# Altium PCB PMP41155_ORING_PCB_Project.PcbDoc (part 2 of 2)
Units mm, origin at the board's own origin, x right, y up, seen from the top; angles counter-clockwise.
Board outline 28 x 74 mm, 6 copper layers (Top Layer, Layer 2, Layer 3, Layer 4, Layer 5, Bottom Layer), stack 1.284 mm thick; 32 components, 11 nets, 88 pads, 180 vias.
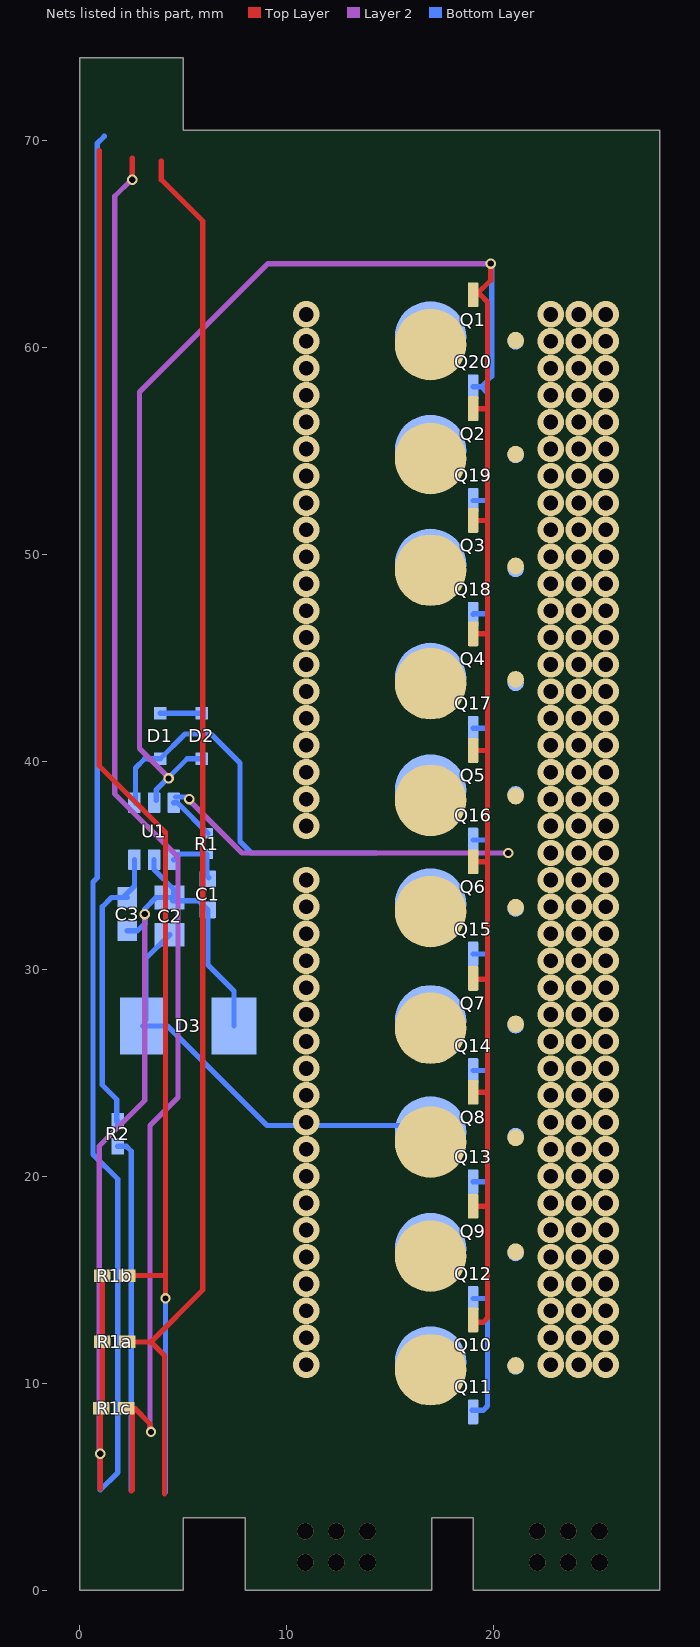
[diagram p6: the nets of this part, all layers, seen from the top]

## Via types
v1: diameter 1.27, hole 0.711, Top Layer to Bottom Layer, 159 vias
v2: diameter 0.8, hole 0.8, Top Layer to Bottom Layer, 12 vias
v3: diameter 0.5, hole 0.3, Top Layer to Bottom Layer, 9 vias

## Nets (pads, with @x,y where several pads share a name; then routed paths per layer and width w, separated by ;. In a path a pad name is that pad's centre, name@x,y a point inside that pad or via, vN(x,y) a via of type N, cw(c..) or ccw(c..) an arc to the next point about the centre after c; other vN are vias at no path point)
CS+_total_charge_current_battery: R1a.2 | length 67.6
  Top Layer w0.254: R1a.2@2.3,12 3.45,12 ; 3.95,69 3.95,68.1 5.95,66.1 5.95,14.5 3.45,12 ; 4.1,4.669 4.1,11.35 3.45,12
CS-_total_charge_current_battery: R1c.2 | length 69
  Top Layer w0.254: 2.5,4.8 2.55,4.85 R1c.2@2.55,8.8 ; v3(2.55,68.1) 2.55,69.15 ; 2.65,8.8 3.4,8.05 v3@3.4,7.8
  Layer 2 w0.254: v3@2.55,68.15 1.7,67.3 1.7,38.45 4.75,35.4 4.75,23.8 3.4,22.45 v3@3.4,7.7
  other v3: 3.452,7.654
NetC1_2: C1.2 R1.1 U1.1 | length 2.9
  Bottom Layer w0.254: U1.1@4.55,35.275 4.825,35.55 R1.1@6.15,35.55 6.15,34.5 C1.2@6.25,34.4
NetC3_1: C3.1 R2.2 U1.3 | length 14.2
  Bottom Layer w0.254: R2.2@1.8,22.65 1.8,23.7 1.1,24.4 1.1,33 1.55,33.45 C3.1@2.3,33.45 ; R2.2@1.85,22.479 R2.2@1.85,22.65 ; C3.1@2.1,33.45 2.65,34 U1.3@2.65,35.275
NetD1_1: D1.1 D2.1 | length 2.1
  Bottom Layer w0.254: D1.1@3.9,42.35 D2.1@5.9,42.35 D2.1@5.95,42.3
ORING_CONTROL: D2.2 Q1.9 Q2.9 Q3.9 Q4.9 Q5.9 Q6.9 Q7.9 Q8.9 Q9.9 Q10.9 Q11.9 Q12.9 Q13.9 Q14.9 Q15.9 Q16.9 Q17.9 Q18.9 Q19.9 Q20.9 U1.5 | length 162.1
  Top Layer w0.254: Q10.9@18.95,12.95 19.5,12.95 19.7,13.15 19.7,18.55 ; Q9.9@19.001,18.55 19.7,18.55 ; Q8.9@19.001,24.05 19.65,24.05 19.7,24.1 ; Q7.9@19.001,29.55 19.05,29.5 19.7,29.5 ; Q6.9@19.001,35.18 19.67,35.18 19.7,35.15 ; Q5.9@19.001,40.55 19.7,40.55 ; Q4.9@19.001,46.18 19.68,46.18 19.7,46.2 ; Q3.9@19.001,51.655 19.695,51.655 19.7,51.65 ; Q2.9@19.001,57.05 19.7,57.05 ; Q1.9@19.2,62.55 19.35,62.55 19.7,62.2 19.7,57.05 ; Q1.9@19.2,62.6 19.85,63.25 v3(19.85,64.05) ; 19.7,18.55 19.7,24.1 ; 19.7,24.1 19.7,29.5 ; 19.7,29.5 19.7,35.15 ; 19.7,35.15 19.7,40.55 ; 19.7,40.55 19.7,46.2 ; 19.7,46.2 19.7,51.65 ; 19.7,51.65 19.7,57.05
  Layer 2 w0.254: v3@4.345,39.205 2.9,40.65 2.9,57.85 9.1,64.05 v3(19.85,64.05)
  Bottom Layer w0.254: U1.5@3.7,38.15 3.7,38.65 5.2,40.15 D2.2@5.9,40.15 ; Q11.9@18.95,8.7 19.5,8.7 19.7,8.9 19.7,25.1 ; Q12.9@19.001,14.095 19.595,14.095 19.6,14.1 ; Q13.9@19.001,19.725 19.625,19.725 19.65,19.75 ; Q14.9@19.001,25.095 19.695,25.095 19.7,25.1 ; Q15.9@19.001,30.725 19.675,30.725 19.7,30.7 ; Q16.9@19.001,36.225 19.675,36.225 19.7,36.2 ; Q17.9@19.001,41.62 19.67,41.62 19.7,41.65 ; Q18.9@19.001,47.12 19.03,47.15 19.65,47.15 ; Q19.9@19.001,52.62 19.62,52.62 19.65,52.65 ; Q20.9@19.001,58.109 19.391,58.109 ; v3@19.9,64.05 19.9,58.618 19.391,58.109 ; 19.391,58.109 19.7,57.8 19.7,41.65 ; 19.7,25.1 19.7,30.7 ; 19.7,30.7 19.7,36.2 ; 19.7,36.2 19.7,41.65
  other v3: 4.3,39.2
SGND: C1.1 C2.2 C3.2 D3.2 R1a.1 R1b.1 R1c.1 U1.2 | length 119
  Top Layer w0.254: 1,4.9 v3(1,6.6) 1,8.55 R1c.1@1.3,8.85 ; R1c.1@1.05,8.8 1.1,8.85 R1a.1@1.1,12 R1b.1@1.1,15.2
  Layer 2 w0.254: v3@0.95,6.65 0.95,21.45 3.15,23.65 v3(3.15,32.65)
  Bottom Layer w0.254: v3(1,6.6) 1,4.85 1.85,5.7 1.85,19.85 0.646,21.054 0.646,24.212 0.646,34.196 0.85,34.4 0.85,69.85 1.2,70.2 ; C3.2@2.3,31.85 2.8,31.85 3.15,32.2 v3(3.15,32.65) 3.15,32.9 3.7,33.45 C2.2@4.35,33.45 ; U1.2@3.6,35.275 3.6,34.8 4.55,33.85 C2.2@4.55,33.4 ; C2.2@4.5,33.3 5.75,33.3 C1.1@6.2,32.85 6.2,30.2 7.46,28.94 D3.2@7.46,27.25
UC_ORING_EN: R2.1 | length 17.1
  Bottom Layer w0.254: R2.1@1.85,21.45 2.25,21.45 2.5,21.2 2.5,4.853
VBAT: R1b.2 | length 67.9
  Top Layer w0.254: 0.95,69.5 0.95,39.8 4.15,36.6 4.15,15.2 ; R1b.2@2.3,15.2 4.15,15.2 ; v3(4.15,14.1) 4.15,15.2
  Bottom Layer w0.254: 4.15,4.73 v3(4.15,14.1)
VORING: Q1.5-6-7-8 Q2.5-6-7-8 Q3.5-6-7-8 Q4.5-6-7-8 Q5.5-6-7-8 Q6.5-6-7-8 Q7.5-6-7-8 Q8.5-6-7-8 Q9.5-6-7-8 Q10.5-6-7-8 Q11.5-6-7-8 Q12.5-6-7-8 Q13.5-6-7-8 Q14.5-6-7-8 Q15.5-6-7-8 Q16.5-6-7-8 Q17.5-6-7-8 Q18.5-6-7-8 Q19.5-6-7-8 Q20.5-6-7-8 R1.2 U1.6 | length 19.4
  Layer 2 w0.254: v3@5.312,38.138 7.85,35.6 v3(20.7,35.6)
  Bottom Layer w0.254: U1.6@4.55,38.025 4.725,38.025 R1.2@6.2,36.55 ; U1.6@4.65,38.3 5.2,38.3 v3(5.3,38.2)
  other v1: 22.75,10.9 24.1,10.9 25.4,10.9 22.75,12.2 24.1,12.2 25.4,12.2 22.75,13.5 24.1,13.5 25.4,13.5 22.75,14.8 24.1,14.8 25.4,14.8 22.75,16.1 24.1,16.1 25.4,16.1 22.75,17.4 24.1,17.4 25.4,17.4 22.75,18.7 24.1,18.7 25.4,18.7 22.75,20 24.1,20 25.4,20 22.75,21.3 24.1,21.3 25.4,21.3 22.75,22.6 24.1,22.6 25.4,22.6 22.75,23.9 24.1,23.9 25.4,23.9 22.75,25.2 24.1,25.2 25.4,25.2 22.75,26.5 24.1,26.5 25.4,26.5 22.75,27.8 24.1,27.8 25.4,27.8 22.75,29.1 24.1,29.1 25.4,29.1 22.75,30.4 24.1,30.4 25.4,30.4 22.75,31.7 24.1,31.7 25.4,31.7 22.75,33 24.1,33 25.4,33 22.75,34.3 24.1,34.3 25.4,34.3 22.75,35.6 24.1,35.6 25.4,35.6 22.75,36.9 24.1,36.9 25.4,36.9 22.75,38.2 24.1,38.2 25.4,38.2 22.75,39.5 24.1,39.5 25.4,39.5 22.75,40.8 24.1,40.8 25.4,40.8 22.75,42.1 24.1,42.1 25.4,42.1 22.75,43.4 24.1,43.4 25.4,43.4 22.75,44.7 24.1,44.7 25.4,44.7 22.75,46 24.1,46 25.4,46 22.75,47.3 24.1,47.3 25.4,47.3 22.75,48.6 24.1,48.6 25.4,48.6 22.75,49.9 24.1,49.9 25.4,49.9 22.75,51.2 24.1,51.2 25.4,51.2 22.75,52.5 24.1,52.5 25.4,52.5 22.75,53.8 24.1,53.8 25.4,53.8 22.75,55.1 24.1,55.1 25.4,55.1 22.75,56.4 24.1,56.4 25.4,56.4 22.75,57.7 24.1,57.7 25.4,57.7 22.75,59 24.1,59 25.4,59 22.75,60.3 24.1,60.3 25.4,60.3 22.75,61.6 24.1,61.6 25.4,61.6
  other v2: 22.1,1.35 23.6,1.35 25.1,1.35 22.1,2.85 23.6,2.85 25.1,2.85
VORING1: C2.1 D1.2 D3.1 Q1.1-2-3-4 Q2.1-2-3-4 Q3.1-2-3-4 Q4.1-2-3-4 Q5.1-2-3-4 Q6.1-2-3-4 Q7.1-2-3-4 Q8.1-2-3-4 Q9.1-2-3-4 Q10.1-2-3-4 Q11.1-2-3-4 Q12.1-2-3-4 Q13.1-2-3-4 Q14.1-2-3-4 Q15.1-2-3-4 Q16.1-2-3-4 Q17.1-2-3-4 Q18.1-2-3-4 Q19.1-2-3-4 Q20.1-2-3-4 U1.4 | length 37.8
  Bottom Layer w0.254: U1.4@2.7,38 2.7,39.7 3.15,40.15 D1.2@3.9,40.15 5.1,41.35 6.35,41.35 7.75,39.95 7.75,36.15 8.3,35.6 14.3,35.6 ; D3.1@3.04,27.25 4.25,27.25 9.05,22.45 10.95,22.45 Q13.1-2-3-4@15.65,22.45 ; D3.1@3.2,27.55 3.2,30.5 C2.1@4.35,31.65
  other v1: 10.95,10.9 10.95,12.2 10.95,13.5 10.95,14.8 10.95,16.1 10.95,17.4 10.95,18.7 10.95,20 10.95,21.3 10.95,22.6 10.95,23.9 10.95,25.2 10.95,26.5 10.95,27.8 10.95,29.1 10.95,30.4 10.95,31.7 10.95,33 10.95,34.3 10.95,36.9 10.95,38.2 10.95,39.5 10.95,40.8 10.95,42.1 10.95,43.4 10.95,44.7 10.95,46 10.95,47.3 10.95,48.6 10.95,49.9 10.95,51.2 10.95,52.5 10.95,53.8 10.95,55.1 10.95,56.4 10.95,57.7 10.95,59 10.95,60.3 10.95,61.6
  other v2: 10.9,1.35 12.4,1.35 13.9,1.35 10.9,2.85 12.4,2.85 13.9,2.85

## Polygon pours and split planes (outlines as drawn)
VORING1 on Top Layer "TOP_LAYER_VORING1_P002" (solid, pour order 2): 16.5,4.5 19.3,7.3 19.3,68.95 18.75,69.5 18.7,69.45 9.3,69.45 6.45,66.6 6.45,6.55 8.5,4.5
VORING on Top Layer "TOP_LAYER_VORING_P001" (solid, pour order 1): 20.55,4.95 20.55,69.15 20.9,69.5 27.1,69.5 27.35,69.25 27.35,4.3 21.2,4.3
VORING on Layer 2 "LAYER_2_VORING_P008" (solid, pour order 8): 20.55,4.95 20.55,69.15 20.9,69.5 27.1,69.5 27.35,69.25 27.35,4.3 21.2,4.3
VORING1 on Layer 2 "LAYER_2_VORING1_P003" (solid, pour order 3): 16.5,4.5 19.3,7.3 19.3,68.95 18.75,69.5 18.7,69.45 9.3,69.45 8.1,68.25 8.1,4.9 8.5,4.5
VORING on Layer 3 "LAYER_3_VORING_P007" (solid, pour order 7): 20.55,4.95 20.55,69.15 20.9,69.5 27.1,69.5 27.35,69.25 27.35,4.3 21.2,4.3
VORING1 on Layer 3 "LAYER_3_VORING1_P000" (solid, pour order 0): 16.5,4.5 19.3,7.3 19.3,68.95 18.75,69.5 18.7,69.45 9.3,69.45 8.1,68.25 8.1,4.9 8.5,4.5
VORING on Layer 4 "LAYER_4_VORING_P009" (solid, pour order 9): 20.55,4.95 20.55,69.15 20.9,69.5 27.1,69.5 27.35,69.25 27.35,4.3 21.2,4.3
VORING1 on Layer 4 "LAYER_4_VORING1_P004" (solid, pour order 4): 16.5,4.5 19.3,7.3 19.3,68.95 18.75,69.5 18.7,69.45 9.3,69.45 8.1,68.25 8.1,4.9 8.5,4.5
VORING on Layer 5 "LAYER_5_VORING_P010" (solid, pour order 10): 20.55,4.95 20.55,69.15 20.9,69.5 27.1,69.5 27.35,69.25 27.35,4.3 21.2,4.3
VORING1 on Layer 5 "LAYER_5_VORING1_P005" (solid, pour order 5): 16.5,4.5 19.3,7.3 19.3,68.95 18.75,69.5 18.7,69.45 9.3,69.45 8.1,68.25 8.1,4.9 8.5,4.5
VORING on Bottom Layer "BOTTOM_LAYER_VORING_P011" (solid, pour order 11): 20.55,4.95 20.55,69.15 20.9,69.5 27.1,69.5 27.35,69.25 27.35,4.3 21.2,4.3
VORING1 on Bottom Layer "BOTTOM_LAYER_VORING1_P006" (solid, pour order 6): 16.5,4.5 19.3,7.3 19.3,68.95 18.75,69.5 18.7,69.45 9.3,69.45 8.1,68.25 8.1,4.9 8.5,4.5

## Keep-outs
Keep-Out Layer:
  text ".Layer_Name" at 14.656,-21.806 h1.52

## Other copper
Top Layer:
  region net VORING1: 16.5,4.5 15.7,5.3 9.3,5.3 8.5,4.5 8.5,0 16.5,0
  region net VORING: 27.5,4.5 26.7,5.3 20.3,5.3 19.5,4.5 19.5,0 27.5,0
  region net VBAT: 0.5,69 0.8,68.7 1.2,68.7 1.5,69 1.5,74 0.5,74
  region net CS-_total_charge_current_battery: 2,69 2.3,68.7 2.7,68.7 3,69 3,74 2,74
  region net CS+_total_charge_current_battery: 3.5,69 3.8,68.7 4.2,68.7 4.5,69 4.5,74 3.5,74
  region net SGND: 1.5,5 1.2,5.3 0.8,5.3 0.5,5 0.5,0 1.5,0
  region net CS+_total_charge_current_battery: 4.5,5 4.2,5.3 3.8,5.3 3.5,5 3.5,0 4.5,0
  region net CS-_total_charge_current_battery: 3,5 2.7,5.3 2.3,5.3 2,5 2,0 3,0
  text ".Layer_Name" at 14.656,-21.806 h1.52
Layer 2:
  region net VORING1: 16.5,4.5 15.7,5.3 9.3,5.3 8.5,4.5 8.5,0 16.5,0
  region net VORING: 27.5,4.5 26.7,5.3 20.3,5.3 19.5,4.5 19.5,0 27.5,0
Layer 3:
  region net VORING1: 16.5,4.5 15.7,5.3 9.3,5.3 8.5,4.5 8.5,0 16.5,0
  region net VORING: 27.5,4.5 26.7,5.3 20.3,5.3 19.5,4.5 19.5,0 27.5,0
Layer 4:
  region net VORING1: 16.5,4.5 15.7,5.3 9.3,5.3 8.5,4.5 8.5,0 16.5,0
  region net VORING: 27.5,4.5 26.7,5.3 20.3,5.3 19.5,4.5 19.5,0 27.5,0
Layer 5:
  region net VORING1: 16.5,4.5 15.7,5.3 9.3,5.3 8.5,4.5 8.5,0 16.5,0
  region net VORING: 27.5,4.5 26.7,5.3 20.3,5.3 19.5,4.5 19.5,0 27.5,0
Bottom Layer:
  region net VORING1: 16.5,4.5 15.7,5.3 9.3,5.3 8.5,4.5 8.5,0 16.5,0
  region net VORING: 27.5,4.5 26.7,5.3 20.3,5.3 19.5,4.5 19.5,0 27.5,0
  region net SGND: 0.5,69 0.8,68.7 1.2,68.7 1.5,69 1.5,74 0.5,74
  region net VBAT: 3.5,5 3.8,5.3 4.2,5.3 4.5,5 4.5,0 3.5,0
  region net UC_ORING_EN: 2,5 2.3,5.3 2.7,5.3 3,5 3,0 2,0
  region net SGND: 0.5,5 0.8,5.3 1.2,5.3 1.5,5 1.5,0 0.5,0
  text ".Layer_Name" at 14.656,-21.806 h1.52

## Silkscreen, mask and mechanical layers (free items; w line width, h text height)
Top Overlay:
  text "PMP41026 RevA" at 10.55,68.15 h2.03
  text "ORING DC" at 11.65,65.55 h2.03
  text ".Layer_Name" at 14.656,-21.806 h1.52
Bottom Overlay:
  text ".Layer_Name" at 14.656,-21.806 h1.52
Top Paste:
  text ".Layer_Name" at 14.656,-21.806 h1.52
Bottom Paste:
  text ".Layer_Name" at 14.656,-21.806 h1.52
Top Solder:
  region: 4.525,4.212 3.498,4.212 3.498,-0.002 4.525,-0.002
  region: 3.025,4.212 1.998,4.212 1.998,-0.002 3.025,-0.002
  region: 1.525,4.212 0.498,4.212 0.498,-0.002 1.525,-0.002
  rectangle: 3.475,69.788 4.502,74.002
  rectangle: 1.975,69.788 3.002,74.002
  rectangle: 0.5,69.786 1.527,74
  rectangle: 19.5,0.015 27.516,4.518
  rectangle: 8.489,-0.004 16.5,4.5
  text ".Layer_Name" at 14.656,-21.806 h1.52
  text ".Layer_Name" at 14.656,-21.806 h1.52
Bottom Solder:
  rectangle: 0.5,69.786 1.5,74
  region: 4.5,4.214 3.5,4.214 3.5,0 4.5,0
  region: 3,4.214 2,4.214 2,0 3,0
  region: 1.5,4.214 0.5,4.214 0.5,0 1.5,0
  rectangle: 19.5,0.015 27.516,4.518
  rectangle: 8.489,-0.004 16.5,4.5
  text ".Layer_Name" at 14.656,-21.806 h1.52
Drill Guide:
  text ".Layer_Name" at 14.656,-21.806 h1.52
M1 Board Outline:
  the board outline again, w0.254
  text ".Layer_Name" at 14.656,-21.806 h1.52
M2 Board Dimensions:
  rectangle: 3.175,-10.16 12.7,-6.985
  rectangle: 0,-6.985 3.175,-3.81
  lines w0.178: 0,-6.985 25.4,-6.985 ; 3.175,-10.16 3.175,-3.81 ; 6.35,-10.16 6.35,-3.81 ; 12.7,-10.16 12.7,-3.81 ; 19.05,-10.16 19.05,-3.81 ; 0,-10.16 0,-3.81 25.4,-3.81 25.4,-10.16 0,-10.16
  text ".Layer_Name" at 14.656,-21.806 h1.52
M3 3D STEP Top:
  text ".Layer_Name" at 14.656,-21.806 h1.52
M4 3D STEP Bottom:
  text ".Layer_Name" at 14.656,-21.806 h1.52
M5 Assembly Top:
  lines w0.254: -7.417,-23.626 160.223,-23.626 ; -7.417,-18.462 160.274,-18.462 ; -7.417,-13.297 -7.417,-28.791 94.31,-28.791 160.274,-28.791 160.274,-13.297 -7.404,-13.297 -7.404,-28.791 32.614,-28.791 ; 55.194,-28.791 55.194,-13.297 ; 87.376,-18.462 87.376,-13.297 ; 108.712,-18.462 108.712,-13.297 ; 124.511,-28.956 124.511,-23.804
  text "COMPONENTS MARKED 'DNP' SHOULD NOT BE POPULATED." at 29.299,-8.09 h1.52
  text "ASSEMBLY VARIANT:" at 29.286,-11.024 h1.52
  text ".VariantName" at 55.601,-11.024 h1.52
  text "PCB VIEWED FROM TOP SIDE" at -5.804,-16.654 h1.52
  text "BOARD #:" at 57.099,-16.654 h1.52
  text ".PRJ_Number" at 70.955,-16.654 h1.52
  text "REV:" at 92.405,-16.654 h1.52
  text ".PCB_Rev" at 99.809,-16.654 h1.52
  text "SVN REV:" at 113.69,-16.654 h1.52
  text ".VersionControl_RevNumber" at 126.543,-16.654 h1.52
  text "TID #:" at 57.099,-21.819 h1.52
  text ".TID" at 70.955,-21.819 h1.52
  text "PLOT NAME =" at -5.804,-27.034 h1.52
  text ".plot_File_Name" at 14.656,-27.034 h1.52
  text "GENERATED    :" at 57.15,-27.034 h1.52
  text ".Print_Date" at 79.235,-27.034 h1.52
  text ".Print_Time" at 97.752,-27.034 h1.52
  text "TEXAS INSTRUMENTS" at 129.87,-27.034 h1.52
M6 Assembly Bottom:
  lines w0.254: -7.429,-18.474 160.261,-18.474 ; -7.379,-23.639 160.261,-23.639 ; 28.334,-28.969 28.334,-23.817 ; 44.133,-18.474 44.133,-13.31 ; 65.468,-18.474 65.468,-13.31 ; 97.65,-28.804 97.65,-13.31 ; 120.231,-28.804 160.249,-28.804 160.249,-13.31 -7.429,-13.31 -7.429,-28.804 58.534,-28.804 160.261,-28.804 160.261,-13.31
  text "COMPONENTS MARKED 'DNP' SHOULD NOT BE POPULATED." at 154.991,-8.077 h1.52
  text ".VariantName" at 128.473,-11.024 h1.52
  text "ASSEMBLY VARIANT:" at 154.864,-11.024 h1.52
  text ".VersionControl_RevNumber" at 26.302,-16.667 h1.52
  text "SVN REV:" at 39.154,-16.667 h1.52
  text ".PCB_Rev" at 53.035,-16.667 h1.52
  text "REV:" at 60.439,-16.667 h1.52
  text ".PRJ_Number" at 81.89,-16.667 h1.52
  text "BOARD #:" at 95.745,-16.667 h1.52
  text "PCB VIEWED FROM BOTTOM SIDE" at 158.648,-16.667 h1.52
  text ".TID" at 81.89,-21.831 h1.52
  text "TID #:" at 95.745,-21.831 h1.52
  text "TEXAS INSTRUMENTS" at 22.974,-27.047 h1.52
  text ".Print_Time" at 55.093,-27.047 h1.52
  text ".Print_Date" at 73.609,-27.047 h1.52
  text "GENERATED    :" at 95.694,-27.047 h1.52
  text ".plot_File_Name" at 138.189,-27.047 h1.52
  text "PLOT NAME =" at 158.648,-27.047 h1.52
M9 Title Sheet:
  drawing of 57 lines, arcs and shapes, not listed
  text "1" at 18.792,204.127 h1.78
  text "2" at 82.182,204.127 h1.78
  text "3" at 145.411,204.127 h1.78
  text "4" at 209.08,204.127 h1.78
  text "5" at 272.555,204.127 h1.78
  text "6" at 336.182,204.127 h1.78
  text "A" at -10.579,175.095 h1.78
  text "A" at 365.341,175.095 h1.78
  text "B" at -10.579,114.643 h1.78
  text "B" at 365.341,114.643 h1.78
  text "C" at -10.579,54.318 h1.78
  text "C" at 365.341,54.318 h1.78
  text "PROJECT TITLE:" at 288.125,7.048 h1.14
  text ".PRJ_Title" at 289.395,3.662 h1.78
  text "DESIGNED FOR:" at 288.125,-0.597 h1.14
  text ".PRJ_Customer" at 289.395,-4.153 h1.78
  text "D" at -10.579,-5.88 h1.78
  text "D" at 365.341,-5.88 h1.78
  text "FILE NAME:" at 288.125,-8.217 h1.14
  text ".PCB_File_Name_No_Path" at 289.395,-11.265 h1.78
  text "Texas Instruments (TI) and/or its licensors do not warrant the accuracy or completeness of this specification" at 161.9,-15.376 h1.14
  text "ENGINEER:" at 288.125,-15.583 h1.14
  text "LAYOUT BY:" at 326.352,-15.583 h1.14
  text "or any information contained therein. TI and/or its licensors do not warrant that this design will meet" at 160.757,-18.237 h1.14
  text ".PRJ_Engineer" at 289.395,-19.52 h1.78
  text ".PCB_Layout" at 327.635,-19.52 h1.78
  text "the specifications, will be suitable for your application or fit for any particular purpose, or will operate in" at 160.757,-21.099 h1.14
  text ".Layer_Name" at 14.656,-21.806 h1.52
  text "ALTIUM DESIGNER VERSION:" at 326.352,-23.457 h1.14
  text "an implementation. TI and/or its licensors do not warrant that the design is production worthy. You should" at 160.757,-23.961 h1.14
  text "completely validate and test your design implementation to confirm the system functionality for your application." at 161.9,-26.822 h1.14
  text ".print_Scale" at 289.395,-26.843 h1.78
  text ".Application_BuildNumber" at 327.635,-26.843 h1.78
  text "1" at 18.792,-32.093 h1.78
  text "2" at 82.182,-32.093 h1.78
  text "3" at 145.411,-32.093 h1.78
  text "4" at 209.08,-32.093 h1.78
  text "5" at 272.555,-32.093 h1.78
  text "6" at 336.182,-32.093 h1.78
M10 Fab Notes:
  drawing of 189 lines, arcs and shapes, not listed
  text "DESIGN INFORMATION" at 314.503,161.447 h1.52
  text "MIN. TRACK WIDTH:" at 298.131,158.091 h1.52
  text "8" at 325.976,158.091 h1.52
  text "MIL" at 329.907,158.091 h1.52
  text "7.874" at 321.75,155 h1.52
  text "MIN. CLEARANCE:" at 298.131,154.938 h1.52
  text "MIL" at 329.907,154.938 h1.52
  text "MIN. VIA PAD SIZE:" at 298.131,151.785 h1.52
  text "24" at 325.214,151.785 h1.52
  text "MIL" at 329.907,151.785 h1.52
  text "0.05mm (2MIL)" at 315.784,148.486 h1.52
  text "MINIMUM ANNULAR RING" at 289.769,148.277 h1.52
  text "EXTERNAL" at 333.768,148.277 h1.52
  text "PER" at 294.849,145.48 h1.52
  text "IPC-D-275 CLASS 2 LEVEL C" at 300.437,145.48 h1.52
  text "MIL, HOLES" at 338.238,142.928 h1.52
  text "+/-" at 328.27,142.709 h1.52
  text "+/-" at 349.961,142.709 h1.52
  text "REGISTRATION TOLERANCES:" at 289.769,142.682 h1.52
  text "METAL" at 320.243,142.682 h1.52
  text "5" at 334.879,142.683 h1.52
  text "3" at 356.037,142.683 h1.52
  text "MIL" at 358.99,142.682 h1.52
  text "HOLE SIZE TOLERANCE (UNLESS OTHERWISE SPECIFIED):" at 289.769,140.185 h1.52
  text "+/-" at 349.961,140.112 h1.52
  text "3" at 356.037,140.085 h1.52
  text "MIL" at 358.99,140.085 h1.52
  text "MATERIAL:" at 287.87,136.589 h1.52
  text "FR-4 High Tg" at 312.926,133.324 h1.52
  text "X" at 309.257,133.122 h1.52
  text "FR-408" at 298.563,133.007 h1.52
  text "OTHER" at 336.358,133.007 h1.52
  text "62 MIL (1.6mm) +/-10%" at 306.694,129.374 h1.52
  text "X" at 303.643,129.312 h1.52
  text "THICKNESS:" at 289.769,129.165 h1.52
  text "OTHER" at 339.33,129.165 h1.52
  text "TOLERANCE:" at 289.769,125.652 h1.52
  text "X" at 311.314,125.652 h1.52
  text "ANSI IPC-6012 TYPE 3 CLASS 2" at 315.836,125.652 h1.52
  text "OTHER +/-" at 315.835,121.989 h1.52
  text "BOW & TWIST:" at 289.769,118.302 h1.52
  text "X" at 311.314,118.302 h1.52
  text "ANSI IPC-6012 TYPE 3 CLASS 2" at 315.836,118.302 h1.52
  text "OTHER +/-" at 315.835,114.576 h1.52
  text "DRILLING:" at 287.87,111.258 h1.52
  text "NC_DRILL FILES" at 332.599,108.586 h1.52
  text "REFERENCE:" at 289.769,108.486 h1.52
  text "X" at 306.463,108.484 h1.52
  text "AS SHOWN" at 310.984,108.486 h1.52
  text "X" at 329.348,108.486 h1.52
  text "OTHER" at 340.168,104.873 h1.52
  text "PTH COPPER THICKNESS:" at 289.761,104.783 h1.52
  text "X" at 318.697,104.783 h1.52
  text "20-30 um" at 321.948,104.783 h1.52
  text "BOARD FINISH:" at 287.87,101.034 h1.52
  text "SILKSCREEN:" at 291.812,98.237 h1.52
  text "X" at 316.14,98.237 h1.52
  text "TOP" at 319.112,98.237 h1.52
  text "X" at 329.094,98.237 h1.52
  text "BOTTOM" at 332.091,98.237 h1.52
  text "SILKSCREEN COLOR:" at 291.812,94.295 h1.52
  text "X" at 316.115,94.295 h1.52
  text "WHITE" at 319.112,94.295 h1.52
  text "OTHER" at 332.091,94.295 h1.52
  text "X" at 319.442,90.652 h1.52
  text "GREEN" at 322.439,90.652 h1.52
  text "OTHER" at 338.136,90.652 h1.52
  text "SOLDER RESIST COLOR:" at 291.812,90.477 h1.52
  text "X" at 319.442,86.734 h1.52
  text "MATTE" at 322.439,86.734 h1.52
  text "SEMI-GLOSS" at 338.125,86.717 h1.52
  text "IMMERSION GOLD (ENIG)" at 314.819,82.345 h1.52
  text "ENEPIG" at 348.793,82.162 h1.52
  text "SURFACE FINISH:" at 287.87,82.136 h1.52
  text "X" at 310.298,82.136 h1.52
  text "IMM. TIN/SILVER OR EQUIV" at 296.24,78.649 h1.52
  text "OTHER" at 332.599,78.549 h1.52
  text "ARRAY/PANEL:" at 287.87,74.602 h1.52
  text "CUT AND TRIM PER M1 BOARD OUTLINE" at 314.819,74.393 h1.52
  text "N.C. ROUTE" at 314.819,70.94 h1.52
  text "X" at 332.295,70.94 h1.52
  text "V. SCORE" at 336.816,70.94 h1.52
  text "CERTIFICATION:" at 287.87,67.66 h1.52
  text "MATERIALS AND WORKMANSHIP FOR ALL PCBS" at 306.285,67.66 h1.52
  text "TO MEET OR EXCEED THE REQUIREMENTS OF:" at 306.285,65.271 h1.52
  text "X" at 297.078,62.003 h1.52
  text "ANSI IPC-A-600F CLASS ->" at 300.329,62.003 h1.52
  text "X" at 342.188,62.003 h1.52
  text "2" at 344.982,62.003 h1.52
  text "1" at 336.981,61.965 h1.52
  text "3" at 353.973,61.965 h1.52
  text "X" at 317.702,58.252 h1.52
  text "RoHS" at 320.953,58.252 h1.52
  text "OTHER" at 337.321,58.252 h1.52
  text "PER ORDER" at 347.407,58.252 h1.52
  text "ALL BOARDS MUST MEET OR EXCEED UL94-V0 REQUIREMENTS." at 288.569,54.345 h1.52
  text "PCB MUST BEAR THE UL94V-0 UL REGISTERED MATERIAL ID NUMBER" at 288.569,51.397 h1.52
  text "ADDITIONAL REQUIREMENTS:" at 287.87,47.094 h1.52
  text "MICROSECTION:" at 289.769,44.373 h1.52
  text "YES" at 312.775,44.373 h1.52
  text "REQUIRED" at 334.657,40.707 h1.52
  text "BARE BOARD ELEC. TEST:" at 289.769,40.634 h1.52
  text "NONE" at 322.935,40.634 h1.52
  text "X" at 331.66,40.634 h1.52
  text "PER ORDER" at 349.693,40.634 h1.52
  text "XX MIL VIAS REQUIRE NON-CONDUCTIVE FILL AND PLANARIZE" at 294.04,35.428 h1.5
  text "XX MIL VIAS REQUIRE CONDUCTIVE FILL AND PLANARIZE" at 294.243,32.787 h1.52
  text "OUTER XX MIL TRACES REQUIRE 50 OHM SINGLE-ENDED IMPEDANCE" at 294.218,28.637 h1.47
  text "LAYER 2 & 3 (INNER LAYERS) XX MIL WIDE, XX MIL SPACE / TRACES REQUIRE 100 OHM DIFFERENTIAL IMPEDANCE" at 294.015,22.65 h1.52
  text ".Layer_Name" at 14.656,-21.806 h1.52
M11 Gerber Information:
  lines w0.254: -7.417,-23.626 160.223,-23.626 ; -7.417,-18.462 160.274,-18.462 ; -7.417,-13.297 -7.417,-28.791 94.31,-28.791 160.274,-28.791 160.274,-13.297 -7.404,-13.297 -7.404,-28.791 32.614,-28.791 ; 55.194,-28.791 55.194,-13.297 ; 87.376,-18.462 87.376,-13.297 ; 108.712,-18.462 108.712,-13.297 ; 124.511,-28.956 124.511,-23.804
  text "ALL ARTWORK VIEWED FROM TOP SIDE" at -5.804,-16.654 h1.52
  text "BOARD #:" at 57.099,-16.654 h1.52
  text ".PRJ_Number" at 70.955,-16.654 h1.52
  text "REV:" at 92.405,-16.654 h1.52
  text ".PCB_Rev" at 99.809,-16.654 h1.52
  text "SVN REV:" at 113.69,-16.654 h1.52
  text ".VersionControl_RevNumber" at 126.543,-16.654 h1.52
  text "LAYER NAME =" at -5.804,-21.806 h1.52
  text "TID #:" at 57.099,-21.819 h1.52
  text ".TID" at 70.955,-21.819 h1.52
  text "PLOT NAME =" at -5.804,-27.034 h1.52
  text ".plot_File_Name" at 14.656,-27.034 h1.52
  text "GENERATED    :" at 57.15,-27.034 h1.52
  text ".Print_Date" at 79.235,-27.034 h1.52
  text ".Print_Time" at 97.752,-27.034 h1.52
  text "TEXAS INSTRUMENTS" at 129.87,-27.034 h1.52
M12 Stackup:
  drawing of 399 lines, arcs and shapes, not listed
  text "Layer" at 128.783,165.862 h1.52
  text "Name" at 139.195,165.862 h1.52
  text "Material" at 162.81,165.862 h1.52
  text "Thickness" at 184.648,165.862 h1.52
  text "Constant" at 201.154,165.862 h1.52
  text "Board Layer Stack" at 215.629,165.862 h1.52
  text "Top Overlay" at 139.195,162.814 h1.52
  text "Top Solder" at 139.195,159.766 h1.52
  text "Solder Resist" at 162.81,159.766 h1.52
  text "6.30mil" at 184.648,159.766 h1.52
  text "3.5" at 201.154,159.766 h1.52
  text "1" at 128.783,156.718 h1.52
  text "Top Layer" at 139.195,156.718 h1.52
  text "2.76mil" at 184.648,156.718 h1.52
  text "Dielectric 1" at 139.195,153.67 h1.52
  text "Core-023" at 162.81,153.67 h1.52
  text "7.50mil" at 184.648,153.67 h1.52
  text "4.2" at 201.154,153.67 h1.52
  text "2" at 128.783,150.622 h1.52
  text "Layer 2" at 139.195,150.622 h1.52
  text "2.76mil" at 184.648,150.622 h1.52
  text "Dielectric 3" at 139.195,147.574 h1.52
  text "Core-023" at 162.81,147.574 h1.52
  text "7.50mil" at 184.648,147.574 h1.52
  text "4.2" at 201.154,147.574 h1.52
  text "3" at 128.783,144.526 h1.52
  text "Layer 3" at 139.195,144.526 h1.52
  text "2.76mil" at 184.648,144.526 h1.52
  text "Dielectric1" at 139.195,141.478 h1.52
  text "Core-009" at 162.81,141.478 h1.52
  text "4.00mil" at 184.648,141.478 h1.52
  text "4.5" at 201.154,141.478 h1.52
  text "4" at 128.783,138.43 h1.52
  text "Layer 4" at 139.195,138.43 h1.52
  text "2.76mil" at 184.648,138.43 h1.52
  text "Dielectric 4" at 139.195,135.382 h1.52
  text "Core-023" at 162.81,135.382 h1.52
  text "7.50mil" at 184.648,135.382 h1.52
  text "4.2" at 201.154,135.382 h1.52
  text "5" at 128.783,132.334 h1.52
  text "Layer 5" at 139.195,132.334 h1.52
  text "2.76mil" at 184.648,132.334 h1.52
  text "Dielectric 2" at 139.195,129.286 h1.52
  text "Core-023" at 162.81,129.286 h1.52
  text "7.50mil" at 184.648,129.286 h1.52
  text "4.2" at 201.154,129.286 h1.52
  text "6" at 128.783,126.238 h1.52
  text "Bottom Layer" at 139.195,126.238 h1.52
  text "2.76mil" at 184.648,126.238 h1.52
  text "Bottom Solder" at 139.195,123.19 h1.52
  text "Solder Resist" at 162.81,123.19 h1.52
  text "6.30mil" at 184.648,123.19 h1.52
  text "3.5" at 201.154,123.19 h1.52
  text "Bottom Overlay" at 139.195,120.142 h1.52
  text ".Layer_Name" at 14.656,-21.806 h1.52
M13 Component Bodies Top:
  text ".Layer_Name" at 14.656,-21.806 h1.52
M14 Component Bodies Bottom:
  text ".Layer_Name" at 14.656,-21.806 h1.52
M15 Courtyards Top:
  text ".Layer_Name" at 14.656,-21.806 h1.52
M16 Courtyards Bottom:
  text ".Layer_Name" at 14.656,-21.806 h1.52
Drill Drawing:
  circle w0.254: c136.238,80.415 r0.702
  lines w0.254: 135.537,77.959 136.94,77.959 136.238,76.556 135.537,77.959 ; 135.537,82.871 136.94,82.871 136.94,84.275 135.537,84.275 135.537,82.871
  lines w0.305: 134.264,75.609 216.344,75.609 ; 134.264,85.082 216.344,85.082 ; 142.846,72.451 142.846,88.24 ; 151.279,72.451 151.279,88.24 ; 167.448,72.451 167.448,88.24 ; 174.03,72.451 174.03,88.24 ; 183.559,72.451 183.559,88.24 ; 201.957,72.451 201.957,88.24 ; 134.264,72.451 216.344,72.451 216.344,88.24 134.264,88.24 134.264,72.451
  text "Symbol" at 136.159,86.029 h1.83
  text "Quantity" at 143.793,86.029 h1.83
  text "Finished Hole Size" at 152.226,86.029 h1.83
  text "Plated" at 168.395,86.029 h1.83
  text "Hole Type" at 174.977,86.029 h1.83
  text "Drill Layer Pair" at 184.506,86.029 h1.83
  text "Hole Tolerance" at 202.904,86.029 h1.83
  text "9" at 143.793,82.871 h1.52
  text "11.81mil (0.300mm)" at 152.226,82.871 h1.52
  text "PTH" at 168.395,82.871 h1.52
  text "Round" at 174.977,82.871 h1.52
  text "Top Layer - Bottom Layer" at 184.506,82.871 h1.52
  text "159" at 143.793,79.714 h1.52
  text "28.00mil (0.711mm)" at 152.226,79.714 h1.52
  text "PTH" at 168.395,79.714 h1.52
  text "Round" at 174.977,79.714 h1.52
  text "Top Layer - Bottom Layer" at 184.506,79.714 h1.52
  text "12" at 143.793,76.556 h1.52
  text "31.50mil (0.800mm)" at 152.226,76.556 h1.52
  text "PTH" at 168.395,76.556 h1.52
  text "Round" at 174.977,76.556 h1.52
  text "Top Layer - Bottom Layer" at 184.506,76.556 h1.52
  text "180 Total" at 143.793,73.398 h1.52
  text ".Layer_Name" at 14.656,-21.806 h1.52
M17 Embedded Cavity:
  text ".Layer_Name" at 14.656,-21.806 h1.52
M18 Embedded Assembly:
  text ".Layer_Name" at 14.656,-21.806 h1.52
M19 Embedded Keepout:
  text ".Layer_Name" at 14.656,-21.806 h1.52

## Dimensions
0,0 to 28,0 on M2 Board Dimensions
0,0 to 5,74 on M2 Board Dimensions
0,-10.16 to 25.4,-10.16 on M2 Board Dimensions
